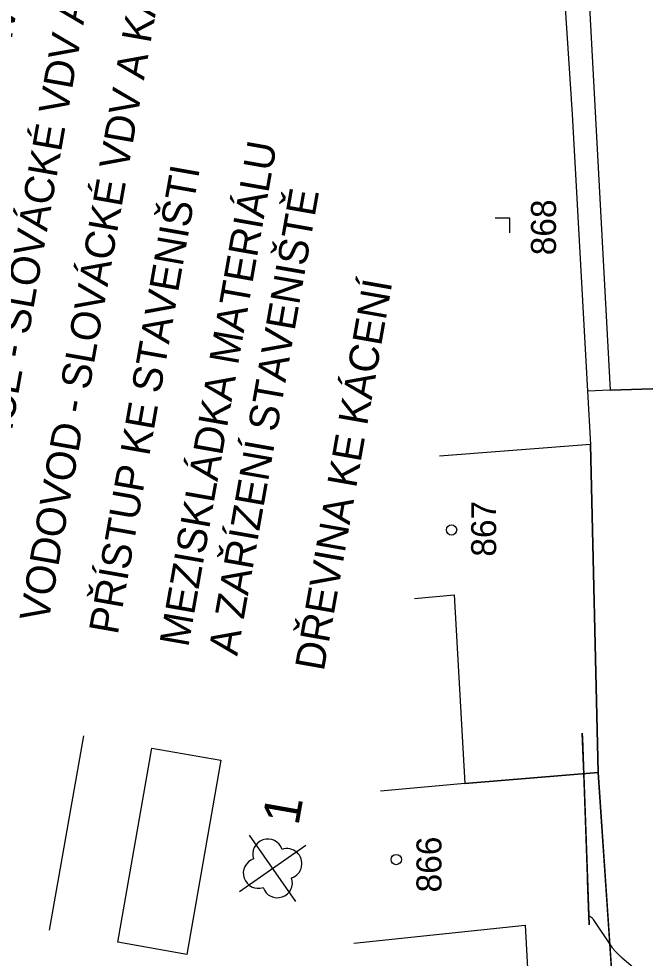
# Model space of a CAD drawing. Extents: x -534481 to -534262, y -1190577 to -1190138.
# Drawn here: x -534379.97 to -534358.66, y -1190186.88 to -1190154.95 of the extents above; entities that cross this region are included whole.
import ezdxf

# ---------------------------------------------------------------- set-up
doc = ezdxf.new("R2010")
doc.units = 0
for name, color, linetype in [('_přístup', 7, 'Continuous'), ('Definiční body', 7, 'Continuous'), ('OMP', 7, 'Continuous'), ('Polygon budovy', 7, 'Continuous'), ('Polygon parcely', 7, 'Continuous'), ('Vrstva 18', 7, 'Continuous'), ('Vrstva 31', 7, 'Continuous'), ('Vrstva 46', 7, 'Continuous'), ('Vrstva 48', 7, 'Continuous'), ('Vrstva 54', 7, 'Continuous')]:
    doc.layers.add(name, color=color, linetype=linetype)

msp = doc.modelspace()

# ---------------------------------------------------------------- linework, layer by layer
at = {"layer": '_přístup'}
msp.add_line((-534378.921, -1190185.933), (-534377.757, -1190179.329), dxfattribs=at)
msp.add_lwpolyline([(-534376.602, -1190186.342), (-534375.438, -1190179.738), (-534373.092, -1190180.152), (-534374.256, -1190186.755)], close=True, dxfattribs=at)
at = {"layer": 'Definiční body'}
for p, q in [((-534360.62, -1190167.61), (-534360.52, -1190169.42)), ((-534360.52, -1190169.42), (-534360.26, -1190180.57)), ((-534360.26, -1190180.57), (-534359.52, -1190191.38))]:
    msp.add_line(p, q, dxfattribs=at)
for points in [[(-534361.51, -1190152.68), (-534361.14, -1190158.2), (-534360.62, -1190167.61)], [(-534356.05, -1190164.42), (-534356.7, -1190164.46), (-534356.61, -1190167.47), (-534359.85, -1190167.58), (-534360.62, -1190167.61)], [(-534360.52, -1190169.42), (-534365.652, -1190169.824)], [(-534360.26, -1190180.57), (-534364.79, -1190180.95), (-534367.658, -1190181.203)]]:
    msp.add_lwpolyline(points, dxfattribs=at)
at = {"layer": 'Polygon parcely'}
msp.add_lwpolyline([(-534359.85, -1190167.58), (-534356.61, -1190167.47), (-534356.7, -1190164.46), (-534356.05, -1190164.42), (-534352.78, -1190164.24), (-534353.43, -1190152.26), (-534353.54, -1190152.27), (-534356.53, -1190152.42), (-534360.66, -1190152.64)], close=True, dxfattribs=at)
for points in [[(-534366.503, -1190174.653), (-534365.16, -1190174.53), (-534364.79, -1190180.95), (-534360.26, -1190180.57), (-534360.52, -1190169.42), (-534365.652, -1190169.824)], [(-534368.569, -1190186.37), (-534362.74, -1190185.76), (-534362.41, -1190191.8), (-534359.52, -1190191.38), (-534360.26, -1190180.57), (-534364.79, -1190180.95), (-534367.658, -1190181.203)]]:
    msp.add_lwpolyline(points, dxfattribs=at)
at = {"layer": 'Vrstva 18'}
msp.add_lwpolyline([(-534358.775, -1190187.444), (-534359.437, -1190186.876), (-534359.455, -1190186.86), (-534359.473, -1190186.844), (-534359.49, -1190186.828), (-534359.508, -1190186.812), (-534359.577, -1190186.746), (-534359.594, -1190186.729), (-534359.611, -1190186.712), (-534359.628, -1190186.696), (-534359.644, -1190186.678), (-534359.71, -1190186.609), (-534359.726, -1190186.592), (-534359.741, -1190186.573), (-534359.756, -1190186.555), (-534359.77, -1190186.535), (-534360.411, -1190185.572), (-534360.424, -1190185.555), (-534360.438, -1190185.539), (-534360.453, -1190185.525), (-534360.47, -1190185.513), (-534360.541, -1190185.465), (-534360.557, -1190185.452), (-534360.568, -1190185.437), (-534360.575, -1190185.419), (-534360.578, -1190185.399), (-534360.738, -1190180.907), (-534360.797, -1190179.233), (-534360.792, -1190179.395), (-534360.566, -1190185.743), (-534360.62, -1190184.241)], dxfattribs=at)
at = {"layer": 'Vrstva 46'}
for centre in [(-534365.245, -1190172.328), (-534367.126, -1190183.529)]:
    msp.add_circle(centre, 0.175, dxfattribs=at)
at = {"layer": 'Vrstva 48'}
for p, q in [((-534363.263, -1190161.724), (-534363.763, -1190161.724)), ((-534363.263, -1190162.225), (-534363.263, -1190161.724))]:
    msp.add_line(p, q, dxfattribs=at)
at = {"layer": 'Vrstva 54'}
for p, q in [((-534370.544, -1190184.958), (-534372.123, -1190182.704)), ((-534372.461, -1190184.62), (-534370.206, -1190183.042))]:
    msp.add_line(p, q, dxfattribs=at)
msp.add_circle((-534371.333, -1190183.831), 0.000512, dxfattribs=at)
for centre, start, end in [((-534371.497, -1190183.346), 18.6209, 198.6209), ((-534370.848, -1190183.668), 288.6209, 108.6209), ((-534371.818, -1190183.995), 108.6209, 288.6209), ((-534371.17, -1190184.316), 198.6209, 18.6209)]:
    msp.add_arc(centre, 0.512, start, end, dxfattribs=at)

# ---------------------------------------------------------------- texts
at = {"layer": 'OMP'}
for s, p in [('TELEKOMUNIKAČNÍ KABEL - AVONET', (-534383.565, -1190174.687)), ('KANALIZACE - SLOVÁCKÉ VDV A KAN.', (-534381.281, -1190175.09)), ('VODOVOD - SLOVÁCKÉ VDV A KAN.', (-534378.962, -1190175.499)), ('MEZISKLÁDKA MATERIÁLU ', (-534374.203, -1190176.338)), ('PŘÍSTUP KE STAVENIŠTI', (-534376.603, -1190175.914)), ('A ZAŘÍZENÍ STAVENIŠTĚ', (-534372.536, -1190176.632)), ('DŘEVINA KE KÁCENÍ', (-534369.592, -1190177.151))]:
    msp.add_text(s, height=1, rotation=79.9998, dxfattribs=at).set_placement(p)
at = {"layer": 'Polygon budovy'}
for s, p in [('868', (-534361.694, -1190162.99)), ('867', (-534363.728, -1190173.234)), ('866', (-534365.589, -1190184.646))]:
    msp.add_text(s, height=0.85, rotation=90, dxfattribs=at).set_placement(p)
at = {"layer": 'Vrstva 31'}
msp.add_text('1', height=1.25, rotation=80, dxfattribs=at).set_placement((-534370.456, -1190182.402))

doc.saveas('drawing.dxf')
